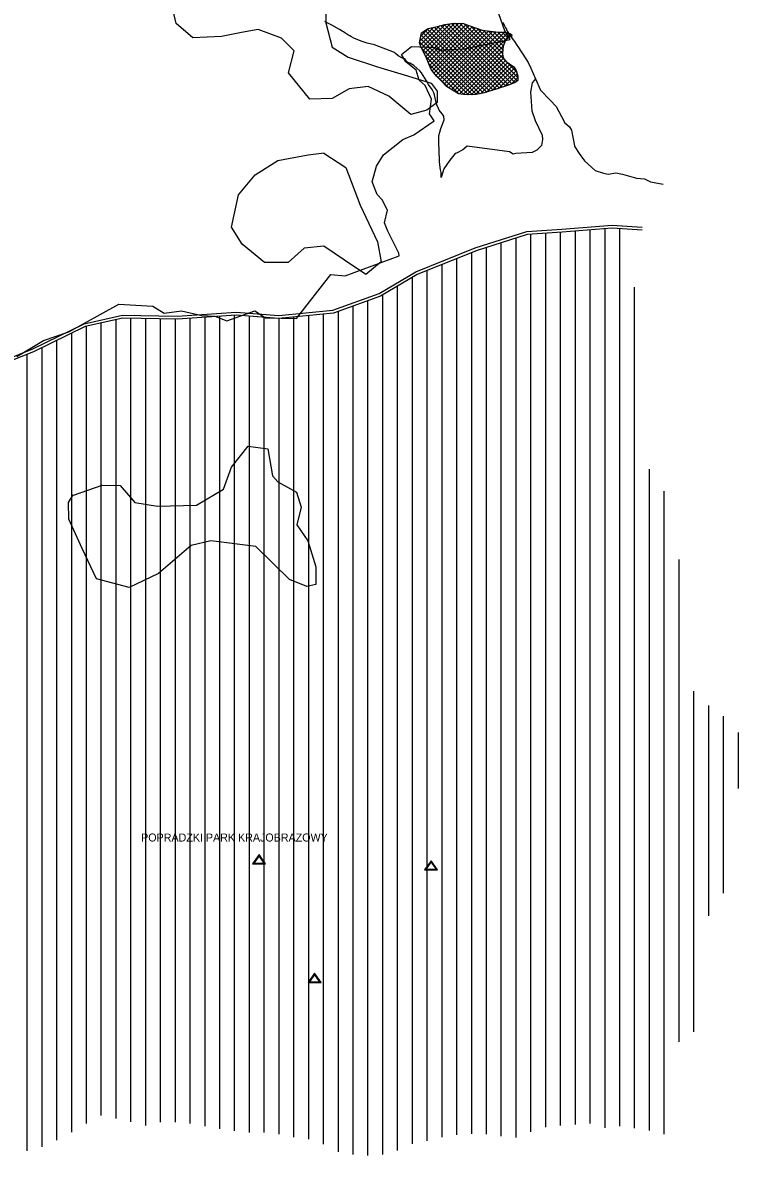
# Model space of a CAD drawing. Extents: x -562861 to -547287, y 190696 to 208158.
# Drawn here: x -551949 to -549533, y 191471 to 195293 of the extents above; entities that cross this region are included whole.
import ezdxf

# ---------------------------------------------------------------- set-up
doc = ezdxf.new("R2010")
doc.units = 0
for name, color, linetype in [('EKO - gr-OChK', 7, 'Continuous'), ('EKO - gr-PPK', 7, 'Continuous'), ('EKO - pomniki przyrody', 7, 'Continuous'), ('EKO - strefa ekologiczna', 7, 'Continuous'), ('EKO1 - osuwiska do 97r', 7, 'Continuous'), ('EKO2 - osuwiska full', 7, 'Continuous'), ('natura_2000', 7, 'Continuous'), ('tur_trasy rowerowe', 7, 'Continuous')]:
    doc.layers.add(name, color=color, linetype=linetype)

msp = doc.modelspace()

# ---------------------------------------------------------------- linework, layer by layer
at = {"layer": 'EKO - gr-OChK'}
msp.add_lwpolyline([(-552062.5, 194132.5), (-551914.5, 194192.5), (-551741.1, 194276.8), (-551611.9, 194305.9), (-551427.1, 194302.1), (-551228.4, 194316.4), (-551084.5, 194305), (-550901.6, 194322.9), (-550745.5, 194378.9), (-550621.9, 194451.8), (-550421.2, 194532.5), (-550247.7, 194587.9), (-550128.8, 194596.4), (-549959.2, 194609.1), (-549857.8, 194603.1)], dxfattribs=at)
at = {"layer": 'EKO - gr-PPK'}
for p, q in [((-550183.4, 191565.8), (-550183.4, 194582.5)), ((-550133.4, 191571.9), (-550133.4, 194586.1)), ((-550083.4, 191575.4), (-550083.4, 194589.8)), ((-550033.4, 191578.6), (-550033.4, 194593.5)), ((-549983.4, 191563.7), (-549983.4, 194597.3)), ((-549933.4, 191568.9), (-549933.4, 194597.6)), ((-550333.4, 191535.6), (-550333.4, 194550)), ((-550283.4, 191531.3), (-550283.4, 194566)), ((-550233.4, 191549.8), (-550233.4, 194578.9)), ((-550433.4, 191542.9), (-550433.4, 194516.8)), ((-550383.4, 191541.8), (-550383.4, 194534.1)), ((-550533.4, 191532.6), (-550533.4, 194476.6)), ((-550483.4, 191539.9), (-550483.4, 194496.7)), ((-550633.4, 191509.4), (-550633.4, 194433.4)), ((-550583.4, 191520), (-550583.4, 194456.5)), ((-550683.4, 191487.1), (-550683.4, 194403.9)), ((-549883.4, 191562.4), (-549883.4, 194400.6)), ((-550783.4, 191470.8), (-550783.4, 194354.7)), ((-550733.4, 191473.1), (-550733.4, 194374.4)), ((-550883.4, 191482.3), (-550883.4, 194318.8)), ((-550833.4, 191473.9), (-550833.4, 194336.7)), ((-551683.4, 191605.5), (-551683.4, 194279.5)), ((-551633.4, 191595.4), (-551633.4, 194290.8)), ((-551583.4, 191584.1), (-551583.4, 194295.3)), ((-551533.4, 191571.3), (-551533.4, 194294.3)), ((-551483.4, 191582.3), (-551483.4, 194293.3)), ((-551433.4, 191582.5), (-551433.4, 194292.2)), ((-551383.4, 191577.7), (-551383.4, 194295.2)), ((-551333.4, 191568.9), (-551333.4, 194298.8)), ((-551283.4, 191560), (-551283.4, 194302.4)), ((-551233.4, 191553.2), (-551233.4, 194306)), ((-551183.4, 191547.6), (-551183.4, 194302.8)), ((-551133.4, 191548.2), (-551133.4, 194298.8)), ((-551083.4, 191542.6), (-551083.4, 194295)), ((-551033.4, 191532.3), (-551033.4, 194299.9)), ((-550983.4, 191524.9), (-550983.4, 194304.8)), ((-550933.4, 191508.1), (-550933.4, 194309.7)), ((-551783.4, 191549), (-551783.4, 194245.1)), ((-551733.4, 191578.5), (-551733.4, 194268.3)), ((-551833.4, 191522.5), (-551833.4, 194220.8)), ((-551933.4, 191486), (-551933.4, 194174)), ((-551883.4, 191500), (-551883.4, 194196.5)), ((-549833.4, 191554.1), (-549833.4, 193786.5)), ((-549783.4, 191541.9), (-549783.4, 193711.5)), ((-549733.4, 191854), (-549733.4, 193481.2)), ((-549683.4, 191887.3), (-549683.4, 193037)), ((-549633.4, 192279), (-549633.4, 192988.7)), ((-549583.4, 192355.8), (-549583.4, 192953.1)), ((-549533.4, 192708.3), (-549533.4, 192897.9))]:
    msp.add_line(p, q, dxfattribs=at)
msp.add_lwpolyline([(-549858.4, 194593.1), (-549959.1, 194599.1), (-550128.1, 194586.4), (-550245.8, 194578), (-550417.8, 194523.1), (-550617.5, 194442.8), (-550741.2, 194369.8), (-550899.3, 194313.1), (-551084.4, 194294.9), (-551228.4, 194306.4), (-551426.8, 194292.1), (-551610.9, 194295.9), (-551737.8, 194267.3), (-551910.4, 194183.3), (-552056.3, 194124.2)], dxfattribs=at)
at = {"layer": 'EKO - pomniki przyrody'}
for points in [[(-551173.1, 192454.6), (-551129, 192454.6), (-551151, 192485.5)], [(-551133.4, 192456.7), (-551151, 192481.4), (-551168.7, 192456.7)], [(-550592.4, 192434.1), (-550548.3, 192434.1), (-550570.4, 192465)], [(-550552.7, 192436.2), (-550570.4, 192460.9), (-550588, 192436.2)], [(-550985.7, 192054.2), (-550941.6, 192054.2), (-550963.6, 192085.1)], [(-550946, 192056.3), (-550963.6, 192081), (-550981.3, 192056.3)]]:
    msp.add_lwpolyline(points, close=True, dxfattribs=at)
at = {"layer": 'EKO - strefa ekologiczna'}
for points in [[(-550585, 194998.1), (-550639.2, 194982.7), (-550712.8, 195044.6), (-550782.5, 195077.6), (-550846.4, 195069.8), (-550904.4, 195036.9), (-550979.9, 195034.9), (-551051.5, 195124), (-551032.2, 195197.6), (-551074.8, 195240.2), (-551154.1, 195269.3), (-551210.2, 195259.6), (-551278, 195246), (-551374.8, 195242.2), (-551430.9, 195290.2), (-551448.3, 195367.7)], [(-550926.8, 195366.7), (-550925.3, 195291.8), (-550904.2, 195209.9), (-550850.5, 195176), (-550751.7, 195143.5), (-550650.1, 195113.8), (-550569.6, 195088.8), (-550549.8, 195062), (-550549.8, 195023.9), (-550584.9, 194997.7)], [(-550932, 194852.2), (-550857.7, 194804.4), (-550809.9, 194676.9), (-550751.5, 194552.9), (-550739.1, 194485.6), (-550790.4, 194443.1), (-550863, 194490.9), (-550932, 194538.7), (-550999.3, 194531.7), (-551052.4, 194483.8), (-551132.1, 194483.8), (-551208.2, 194545.8), (-551243.6, 194602.5), (-551220.6, 194712.3), (-551163.9, 194779.6), (-551087.8, 194827.4), (-550985.1, 194846.9), (-550931, 194853.9)], [(-551777.8, 193698.3), (-551680.7, 193732.2), (-551620.2, 193730.7), (-551570.1, 193673.2), (-551493.4, 193661.4), (-551362.3, 193664.4), (-551270.9, 193718.9), (-551244.3, 193792.7), (-551188.3, 193863.5), (-551121.3, 193854.6), (-551105.8, 193763.2), (-551088.1, 193744), (-551024.7, 193708.6), (-551008.5, 193658.5), (-551023.2, 193598), (-550986.4, 193544.9), (-550959.8, 193456.4), (-550959.8, 193397.4), (-550989.3, 193390), (-551048.3, 193413.6), (-551161.8, 193525.7), (-551313.6, 193544.9), (-551379.9, 193528.7), (-551490.5, 193434.3), (-551589.3, 193387.1), (-551699.8, 193416.6), (-551748.5, 193518.4), (-551792.7, 193617.2), (-551794.2, 193673.2), (-551778.1, 193699.2)]]:
    msp.add_lwpolyline(points, dxfattribs=at)
at = {"layer": 'EKO1 - osuwiska do 97r'}
for p, q in [((-550608, 195230.2), (-550560.9, 195277.3)), ((-550606.5, 195217.5), (-550542.1, 195281.9)), ((-550604.6, 195247.7), (-550579.6, 195272.7)), ((-550602.6, 195207.2), (-550523.1, 195286.8)), ((-550597.9, 195197.8), (-550506.3, 195289.4)), ((-550593.2, 195188.4), (-550490.2, 195291.4)), ((-550588.5, 195179), (-550476.5, 195291)), ((-550584.4, 195168.9), (-550462.8, 195290.6)), ((-550582, 195271.4), (-550372, 195061.4)), ((-550580.3, 195158.8), (-550452.3, 195286.9)), ((-550576.2, 195148.8), (-550442.2, 195282.9)), ((-550572.2, 195138.7), (-550431.6, 195279.3)), ((-550571.2, 195274.8), (-550361.1, 195064.6)), ((-550566.8, 195129.9), (-550421, 195275.8)), ((-550560.6, 195122), (-550410.4, 195272.2)), ((-550559.8, 195277.5), (-550350.3, 195067.9)), ((-550548.5, 195280.3), (-550339.7, 195071.5)), ((-550537.2, 195283.2), (-550329.1, 195075.1)), ((-550526, 195286.1), (-550318.6, 195078.7)), ((-550514, 195288.2), (-550308, 195082.3)), ((-550501.8, 195290.1), (-550298, 195086.4)), ((-550488.8, 195291.3), (-550288.1, 195090.7)), ((-550474.2, 195290.9), (-550279.9, 195096.5)), ((-550458.6, 195289.4), (-550277.4, 195108.2)), ((-550435.8, 195280.7), (-550282.1, 195127.1)), ((-550414.5, 195273.6), (-550329.7, 195188.8)), ((-550606.3, 195239.1), (-550417.4, 195050.2)), ((-550604, 195250.9), (-550405.6, 195052.6)), ((-550599.4, 195260.5), (-550393.9, 195055)), ((-550590.7, 195265.9), (-550382.8, 195058.1)), ((-550554.3, 195114.1), (-550400, 195268.5)), ((-550547.5, 195106.9), (-550387.8, 195266.5)), ((-550540.4, 195099.8), (-550375.4, 195264.8)), ((-550533.4, 195092.7), (-550362.9, 195263.1)), ((-550526.5, 195085.4), (-550350.5, 195261.4)), ((-550519.6, 195078.1), (-550337.3, 195260.5)), ((-550510.9, 195072.7), (-550323.2, 195260.5)), ((-550501.9, 195067.6), (-550311.2, 195258.3)), ((-550492.9, 195062.5), (-550300.9, 195254.4)), ((-550394.1, 195267.4), (-550328.9, 195202.1)), ((-550377.7, 195265.1), (-550326.5, 195213.9)), ((-550361.3, 195262.9), (-550322.8, 195224.3)), ((-550344.9, 195260.6), (-550318.2, 195233.9)), ((-550330.6, 195260.5), (-550311.7, 195241.5)), ((-550315.3, 195259.3), (-550302, 195246)), ((-550608.6, 195227.2), (-550430.9, 195049.6)), ((-550602.6, 195207.1), (-550444.6, 195049.1)), ((-550484.1, 195057), (-550326, 195215.1)), ((-550474.7, 195052.4), (-550329.2, 195197.9)), ((-550588.4, 195178.8), (-550459.6, 195050)), ((-550462.5, 195050.4), (-550329.2, 195183.7)), ((-550449.4, 195049.3), (-550326, 195172.7)), ((-550435.2, 195049.4), (-550319.7, 195164.9)), ((-550420.5, 195049.9), (-550311.9, 195158.5)), ((-550578.8, 195155), (-550476.4, 195052.7)), ((-550563, 195125.1), (-550510.3, 195072.4)), ((-550403.2, 195053.1), (-550303.6, 195152.7)), ((-550384.7, 195057.5), (-550295.3, 195146.8)), ((-550364.4, 195063.7), (-550288.5, 195139.5)), ((-550343.8, 195070.1), (-550283.3, 195130.6)), ((-550322.3, 195077.4), (-550279.8, 195120)), ((-550300.1, 195085.5), (-550277.4, 195108.2))]:
    msp.add_line(p, q, dxfattribs=at)
msp.add_lwpolyline([(-550297.8, 195247.3), (-550310, 195243.5), (-550320.4, 195231.3), (-550326.9, 195212.5), (-550328.8, 195203.1), (-550329.8, 195189.1), (-550328.8, 195179.7), (-550325.1, 195170.3), (-550316.6, 195161.8), (-550291.2, 195144), (-550283.7, 195131.7), (-550277.1, 195112), (-550278.1, 195097.9), (-550286.5, 195091.3), (-550306.3, 195082.9), (-550350.5, 195067.9), (-550390.9, 195055.6), (-550418.2, 195050), (-550445.4, 195049.1), (-550460.5, 195050), (-550477.4, 195052.8), (-550492.4, 195062.2), (-550518.8, 195077.3), (-550535.7, 195095.1), (-550552.6, 195112), (-550570.5, 195134.6), (-550588.4, 195178.7), (-550603.4, 195208.8), (-550609, 195224.8), (-550602.5, 195258.6), (-550579.9, 195272.7), (-550548.9, 195280.2), (-550523.5, 195286.8), (-550493.4, 195291.5), (-550461.4, 195290.5), (-550442.6, 195283), (-550417.2, 195274.5), (-550398.4, 195268), (-550371.1, 195264.2), (-550343.9, 195260.5), (-550320.4, 195260.5), (-550304.4, 195256.7), (-550298.7, 195252.9)], close=True, dxfattribs=at)
at = {"layer": 'EKO2 - osuwiska full'}
for p, q in [((-550608, 195230.2), (-550560.9, 195277.3)), ((-550606.5, 195217.5), (-550542.1, 195281.9)), ((-550604.6, 195247.7), (-550579.6, 195272.7)), ((-550602.6, 195207.2), (-550523.1, 195286.8)), ((-550597.9, 195197.8), (-550506.3, 195289.4)), ((-550593.2, 195188.4), (-550490.2, 195291.4)), ((-550588.5, 195179), (-550476.5, 195291)), ((-550584.4, 195168.9), (-550462.8, 195290.6)), ((-550582, 195271.4), (-550372, 195061.4)), ((-550580.3, 195158.8), (-550452.3, 195286.9)), ((-550576.2, 195148.8), (-550442.2, 195282.9)), ((-550572.2, 195138.7), (-550431.6, 195279.3)), ((-550571.2, 195274.8), (-550361.1, 195064.6)), ((-550566.8, 195129.9), (-550421, 195275.8)), ((-550560.6, 195122), (-550410.4, 195272.2)), ((-550559.8, 195277.5), (-550350.3, 195067.9)), ((-550548.5, 195280.3), (-550339.7, 195071.5)), ((-550537.2, 195283.2), (-550329.1, 195075.1)), ((-550526, 195286.1), (-550318.6, 195078.7)), ((-550514, 195288.2), (-550308, 195082.3)), ((-550501.8, 195290.1), (-550298, 195086.4)), ((-550488.8, 195291.3), (-550288.1, 195090.7)), ((-550474.2, 195290.9), (-550279.9, 195096.5)), ((-550458.6, 195289.4), (-550277.4, 195108.2)), ((-550435.8, 195280.7), (-550282.1, 195127.1)), ((-550414.5, 195273.6), (-550329.7, 195188.8)), ((-550606.3, 195239.1), (-550417.4, 195050.2)), ((-550604, 195250.9), (-550405.6, 195052.6)), ((-550599.4, 195260.5), (-550393.9, 195055)), ((-550590.7, 195265.9), (-550382.8, 195058.1)), ((-550554.3, 195114.1), (-550400, 195268.5)), ((-550547.5, 195106.9), (-550387.8, 195266.5)), ((-550540.4, 195099.8), (-550375.4, 195264.8)), ((-550533.4, 195092.7), (-550362.9, 195263.1)), ((-550526.5, 195085.4), (-550350.5, 195261.4)), ((-550519.6, 195078.1), (-550337.3, 195260.5)), ((-550510.9, 195072.7), (-550323.2, 195260.5)), ((-550501.9, 195067.6), (-550311.2, 195258.3)), ((-550492.9, 195062.5), (-550300.9, 195254.4)), ((-550394.1, 195267.4), (-550328.9, 195202.1)), ((-550377.7, 195265.1), (-550326.5, 195213.9)), ((-550361.3, 195262.9), (-550322.8, 195224.3)), ((-550344.9, 195260.6), (-550318.2, 195233.9)), ((-550330.6, 195260.5), (-550311.7, 195241.5)), ((-550315.3, 195259.3), (-550302, 195246)), ((-550608.6, 195227.2), (-550430.9, 195049.6)), ((-550602.6, 195207.1), (-550444.6, 195049.1)), ((-550484.1, 195057), (-550326, 195215.1)), ((-550474.7, 195052.4), (-550329.2, 195197.9)), ((-550588.4, 195178.8), (-550459.6, 195050)), ((-550462.5, 195050.4), (-550329.2, 195183.7)), ((-550449.4, 195049.3), (-550326, 195172.7)), ((-550435.2, 195049.4), (-550319.7, 195164.9)), ((-550420.5, 195049.9), (-550311.9, 195158.5)), ((-550578.8, 195155), (-550476.4, 195052.7)), ((-550563, 195125.1), (-550510.3, 195072.4)), ((-550403.2, 195053.1), (-550303.6, 195152.7)), ((-550384.7, 195057.5), (-550295.3, 195146.8)), ((-550364.4, 195063.7), (-550288.5, 195139.5)), ((-550343.8, 195070.1), (-550283.3, 195130.6)), ((-550322.3, 195077.4), (-550279.8, 195120)), ((-550300.1, 195085.5), (-550277.4, 195108.2))]:
    msp.add_line(p, q, dxfattribs=at)
msp.add_lwpolyline([(-550297.8, 195247.3), (-550310, 195243.5), (-550320.4, 195231.3), (-550326.9, 195212.5), (-550328.8, 195203.1), (-550329.8, 195189.1), (-550328.8, 195179.7), (-550325.1, 195170.3), (-550316.6, 195161.8), (-550291.2, 195144), (-550283.7, 195131.7), (-550277.1, 195112), (-550278.1, 195097.9), (-550286.5, 195091.3), (-550306.3, 195082.9), (-550350.5, 195067.9), (-550390.9, 195055.6), (-550418.2, 195050), (-550445.4, 195049.1), (-550460.5, 195050), (-550477.4, 195052.8), (-550492.4, 195062.2), (-550518.8, 195077.3), (-550535.7, 195095.1), (-550552.6, 195112), (-550570.5, 195134.6), (-550588.4, 195178.7), (-550603.4, 195208.8), (-550609, 195224.8), (-550602.5, 195258.6), (-550579.9, 195272.7), (-550548.9, 195280.2), (-550523.5, 195286.8), (-550493.4, 195291.5), (-550461.4, 195290.5), (-550442.6, 195283), (-550417.2, 195274.5), (-550398.4, 195268), (-550371.1, 195264.2), (-550343.9, 195260.5), (-550320.4, 195260.5), (-550304.4, 195256.7), (-550298.7, 195252.9)], close=True, dxfattribs=at)
at = {"layer": 'natura_2000'}
msp.add_lwpolyline([(-551968.2, 194166.4), (-551879, 194220.6), (-551792.8, 194250.1), (-551623.8, 194342.6), (-551509.2, 194336.5), (-551470.9, 194312.4), (-551412.6, 194320.5), (-551344.2, 194304.4), (-551299.9, 194302.4), (-551259.7, 194286.3), (-551165.2, 194320.5), (-551128.9, 194296.3), (-551024.3, 194294.3), (-550908.3, 194443.5), (-550860.9, 194439), (-550678.2, 194505.6), (-550679.1, 194515.5), (-550716, 194588.9), (-550727.1, 194617.9), (-550717.1, 194660.2), (-550735, 194695.3), (-550752.9, 194712.5), (-550769.4, 194755.5), (-550755, 194808.5), (-550731.4, 194847.2), (-550665.5, 194898.1), (-550628.2, 194913.9), (-550560.1, 194961.2), (-550575.9, 194985.5), (-550569.5, 195034.2), (-550590.2, 195080.8), (-550611, 195098.7), (-550621.1, 195132.4), (-550655.4, 195160.4), (-550670.5, 195185.4), (-550636.1, 195212), (-550555.8, 195209.1), (-550542.2, 195200.5), (-550458.4, 195204.8), (-550303.6, 195236.3), (-550321.5, 195265), (-550341.6, 195322.3)], dxfattribs=at)
at = {"layer": 'tur_trasy rowerowe'}
msp.add_line((-550318.9, 195275.9), (-550316.4, 195271.4), dxfattribs=at)
for points in [[(-550905.8, 195284.7), (-550907.7, 195285.7), (-550911.9, 195288), (-550918.6, 195291.4), (-550929.5, 195296.8)], [(-550905.8, 195284.7), (-550907.7, 195285.7), (-550911.9, 195288), (-550918.6, 195291.4), (-550929.5, 195296.8)], [(-550693.8, 195192.7), (-550761.5, 195218.3), (-550786.3, 195223.8), (-550805.9, 195230.3), (-550830.6, 195240.6), (-550839.5, 195245.4), (-550844.4, 195248), (-550848.9, 195250.8), (-550851.3, 195252.3), (-550858.3, 195256.6), (-550861.9, 195258.9), (-550866.4, 195261.7), (-550870.6, 195264.3), (-550879.1, 195269.4), (-550905.8, 195284.7)], [(-550693.8, 195192.7), (-550761.5, 195218.3), (-550786.3, 195223.8), (-550805.9, 195230.3), (-550830.6, 195240.6), (-550839.5, 195245.4), (-550844.4, 195248), (-550848.9, 195250.8), (-550851.3, 195252.3), (-550858.3, 195256.6), (-550861.9, 195258.9), (-550866.4, 195261.7), (-550870.6, 195264.3), (-550879.1, 195269.4), (-550905.8, 195284.7)], [(-550329.8, 195292.9), (-550327.1, 195289.6), (-550324.3, 195285.4), (-550322.1, 195282), (-550318.9, 195275.9)], [(-550316.4, 195271.4), (-550315.4, 195269.6), (-550313.5, 195264.5), (-550299.7, 195244.2)], [(-550299.7, 195244.2), (-550292.2, 195233.3), (-550289.2, 195229), (-550281, 195217), (-550278.1, 195212.9)], [(-550278.1, 195212.9), (-550250.9, 195170.9), (-550242.7, 195158.6), (-550234.1, 195139.6), (-550218.2, 195103), (-550201.3, 195065.5), (-550168.9, 195031), (-550147.8, 195009.4)], [(-550662.7, 195171.3), (-550667.4, 195173), (-550681.3, 195181.4), (-550690, 195188.9), (-550693.8, 195192.7)], [(-550662.7, 195171.3), (-550667.4, 195173), (-550681.3, 195181.4), (-550690, 195188.9), (-550693.8, 195192.7)], [(-550648.5, 195158.2), (-550655, 195163.5), (-550659.5, 195170.9), (-550662.7, 195171.3)], [(-550648.5, 195158.2), (-550655, 195163.5), (-550659.5, 195170.9), (-550662.7, 195171.3)], [(-550603.2, 195123.1), (-550608.7, 195130.4), (-550628.7, 195148.3), (-550642.1, 195155.9), (-550648.5, 195158.2)], [(-550603.2, 195123.1), (-550608.7, 195130.4), (-550628.7, 195148.3), (-550642.1, 195155.9), (-550648.5, 195158.2)], [(-550554.3, 195027.5), (-550558.5, 195049), (-550561.5, 195056.2), (-550567, 195067.8), (-550579.3, 195084.1), (-550586.2, 195096.1), (-550603.2, 195123.1)], [(-550554.3, 195027.5), (-550558.5, 195049), (-550561.5, 195056.2), (-550567, 195067.8), (-550579.3, 195084.1), (-550586.2, 195096.1), (-550603.2, 195123.1)], [(-550218.2, 195103), (-550229.8, 195089.3), (-550235.1, 195058), (-550230.6, 194994.8), (-550218.6, 194962.7), (-550195.5, 194913.6), (-550194.3, 194898.3), (-550198, 194878.5), (-550213.3, 194862.4), (-550229.3, 194854.6), (-550284.6, 194851.5), (-550292.9, 194848.8)], [(-550218.2, 195103), (-550229.8, 195089.3), (-550235.1, 195058), (-550230.6, 194994.8), (-550218.6, 194962.7), (-550195.5, 194913.6), (-550194.3, 194898.3), (-550198, 194878.5), (-550213.3, 194862.4), (-550229.3, 194854.6), (-550284.6, 194851.5), (-550292.9, 194848.8)], [(-550536.7, 194770.3), (-550536.8, 194779.1), (-550535.9, 194787.3), (-550539.2, 194796.6), (-550541.9, 194821.8), (-550543.1, 194866.1), (-550543.8, 194882.7), (-550544, 194912.1), (-550540.7, 194923.5), (-550537.1, 194936), (-550534.9, 194941.6), (-550526.3, 194965.3), (-550527.2, 194977.2), (-550529.8, 194980.8), (-550533.2, 194985.3), (-550543.1, 194998), (-550545.3, 195003.4), (-550550.6, 195015.7), (-550554.3, 195027.5)], [(-550536.7, 194770.3), (-550536.8, 194779.1), (-550535.9, 194787.3), (-550539.2, 194796.6), (-550541.9, 194821.8), (-550543.1, 194866.1), (-550543.8, 194882.7), (-550544, 194912.1), (-550540.7, 194923.5), (-550537.1, 194936), (-550534.9, 194941.6), (-550526.3, 194965.3), (-550527.2, 194977.2), (-550529.8, 194980.8), (-550533.2, 194985.3), (-550543.1, 194998), (-550545.3, 195003.4), (-550550.6, 195015.7), (-550554.3, 195027.5)], [(-550147.8, 195009.4), (-550121.7, 194959.9), (-550120.6, 194956.3), (-550103.7, 194941.1)], [(-550103.7, 194941.1), (-550096.3, 194930.3), (-550086.8, 194877.6), (-550085.7, 194874.1), (-550071.2, 194851.3), (-550052.3, 194827), (-550016.2, 194794.5), (-549988.9, 194785), (-549972.7, 194782)], [(-550449.2, 194875.7), (-550463.7, 194863.2), (-550484.1, 194852.4), (-550489.4, 194851.3), (-550507.6, 194829.2), (-550527.9, 194799.7), (-550536.7, 194770.3)], [(-550449.2, 194875.7), (-550463.7, 194863.2), (-550484.1, 194852.4), (-550489.4, 194851.3), (-550507.6, 194829.2), (-550527.9, 194799.7), (-550536.7, 194770.3)], [(-550292.9, 194848.8), (-550305.5, 194857.1), (-550449.2, 194875.7)], [(-550292.9, 194848.8), (-550305.5, 194857.1), (-550449.2, 194875.7)], [(-549972.7, 194782), (-549947.2, 194786.4), (-549924.1, 194781.2), (-549876.7, 194768), (-549850.7, 194765.6), (-549829.4, 194755.3), (-549786.7, 194747.7)]]:
    msp.add_lwpolyline(points, dxfattribs=at)

# ---------------------------------------------------------------- texts
at = {"layer": 'EKO - gr-PPK'}
msp.add_text('POPRADZKI PARK KRAJOBRAZOWY', height=27, dxfattribs=at).set_placement((-551549, 192529.8))

doc.saveas('drawing.dxf')
